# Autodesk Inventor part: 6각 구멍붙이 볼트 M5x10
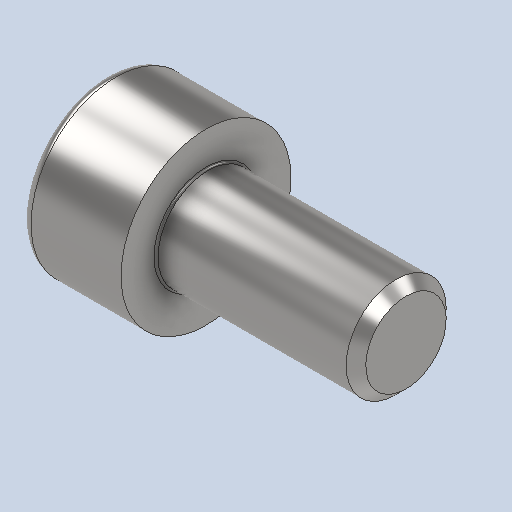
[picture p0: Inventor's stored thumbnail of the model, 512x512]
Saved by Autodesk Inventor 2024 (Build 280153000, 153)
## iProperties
Created: 2026-01
Part Number: 6각 구멍붙이 볼트 M5x10
Material: 강철, 연강
Description: 6각머리 태핑 나사
Document SubType Name: Modeling
Designer: 2-10
Density: 7.85 g/cm^3
Appearance: 기본값
Author: jhkim
Sending System: Autodesk Inventor 2026
Preprocessor: ST-DEVELOPER v20.1
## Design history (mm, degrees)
node "6각 구멍붙이 볼트 M5x101"
node "솔리드1"
body "Solid1"
